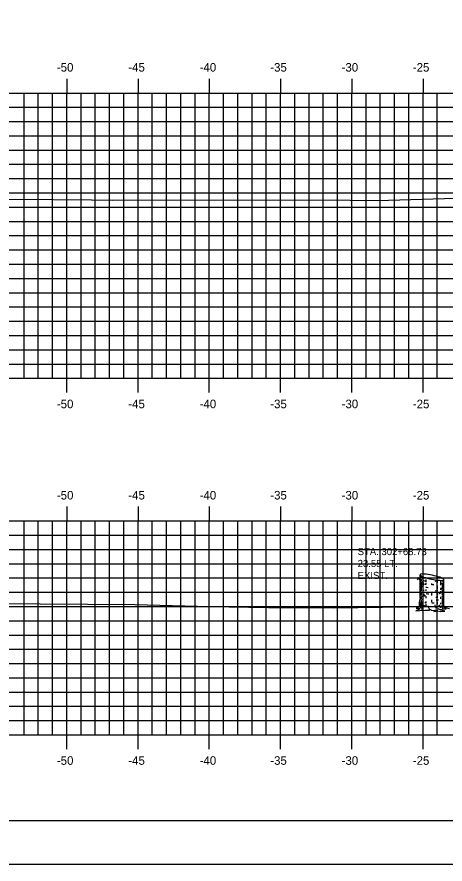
# Model space of a CAD drawing. Extents: x 1136767 to 1136937, y 608981 to 609091.
# Drawn here: x 1136796.9 to 1136826.9, y 608981.3 to 609040.7 of the extents above; entities that cross this region are included whole.
import ezdxf

# ---------------------------------------------------------------- set-up
doc = ezdxf.new("R2010")
doc.units = 0
for name, color, linetype in [('BORDER', 7, 'Continuous'), ('D_Text_Monospaced', 7, 'Continuous'), ('H_V ANNOTATION', 7, 'Continuous'), ('MAJOR', 7, 'Continuous'), ('MINOR', 7, 'Continuous'), ('PLOT BOUNDARY', 7, 'Continuous'), ('S_Roadway_Centerline', 7, 'Continuous'), ('S_Trees_Conifer_Pay', 7, 'Continuous')]:
    doc.layers.add(name, color=color, linetype=linetype)

msp = doc.modelspace()

# ---------------------------------------------------------------- linework, layer by layer
at = {"layer": 'BORDER'}
msp.add_lwpolyline([(1136775.383, 608984.335), (1136935.383, 608984.335), (1136935.383, 609089.335), (1136775.383, 609089.335)], close=True, dxfattribs=at)
at = {"layer": 'MAJOR'}
for p, q in [((1136800.383, 609036.337), (1136800.383, 609035.335)), ((1136805.383, 609036.337), (1136805.383, 609035.335)), ((1136810.383, 609036.337), (1136810.383, 609035.335)), ((1136815.383, 609036.337), (1136815.383, 609035.335)), ((1136820.383, 609036.337), (1136820.383, 609035.335)), ((1136825.383, 609036.337), (1136825.383, 609035.335)), ((1136780.383, 609035.335), (1136920.383, 609035.335)), ((1136780.383, 609035.335), (1136920.383, 609035.335)), ((1136800.383, 609015.335), (1136800.383, 609035.335)), ((1136805.383, 609015.335), (1136805.383, 609035.335)), ((1136810.383, 609015.335), (1136810.383, 609035.335)), ((1136815.383, 609015.335), (1136815.383, 609035.335)), ((1136820.383, 609015.335), (1136820.383, 609035.335)), ((1136825.383, 609015.335), (1136825.383, 609035.335)), ((1136780.383, 609030.335), (1136920.383, 609030.335)), ((1136780.383, 609025.335), (1136920.383, 609025.335)), ((1136780.383, 609020.335), (1136920.383, 609020.335)), ((1136780.383, 609015.335), (1136920.383, 609015.335)), ((1136780.383, 609015.335), (1136920.383, 609015.335)), ((1136800.383, 609014.333), (1136800.383, 609015.335)), ((1136805.383, 609014.333), (1136805.383, 609015.335)), ((1136810.383, 609014.333), (1136810.383, 609015.335)), ((1136815.383, 609014.333), (1136815.383, 609015.335)), ((1136820.383, 609014.333), (1136820.383, 609015.335)), ((1136825.383, 609014.333), (1136825.383, 609015.335)), ((1136800.383, 609006.337), (1136800.383, 609005.335)), ((1136805.383, 609006.337), (1136805.383, 609005.335)), ((1136810.383, 609006.337), (1136810.383, 609005.335)), ((1136815.383, 609006.337), (1136815.383, 609005.335)), ((1136820.383, 609006.337), (1136820.383, 609005.335)), ((1136825.383, 609006.337), (1136825.383, 609005.335)), ((1136780.383, 609005.335), (1136920.383, 609005.335)), ((1136780.383, 609005.335), (1136920.383, 609005.335)), ((1136800.383, 608990.335), (1136800.383, 609005.335)), ((1136805.383, 608990.335), (1136805.383, 609005.335)), ((1136810.383, 608990.335), (1136810.383, 609005.335)), ((1136815.383, 608990.335), (1136815.383, 609005.335)), ((1136820.383, 608990.335), (1136820.383, 609005.335)), ((1136825.383, 608990.335), (1136825.383, 609005.335)), ((1136780.383, 609000.335), (1136920.383, 609000.335)), ((1136780.383, 608995.335), (1136920.383, 608995.335)), ((1136780.383, 608990.335), (1136920.383, 608990.335)), ((1136780.383, 608990.335), (1136920.383, 608990.335)), ((1136800.383, 608989.333), (1136800.383, 608990.335)), ((1136805.383, 608989.333), (1136805.383, 608990.335)), ((1136810.383, 608989.333), (1136810.383, 608990.335)), ((1136815.383, 608989.333), (1136815.383, 608990.335)), ((1136820.383, 608989.333), (1136820.383, 608990.335)), ((1136825.383, 608989.333), (1136825.383, 608990.335))]:
    msp.add_line(p, q, dxfattribs=at)
at = {"layer": 'MINOR'}
for p, q in [((1136797.383, 609015.335), (1136797.383, 609035.335)), ((1136798.383, 609015.335), (1136798.383, 609035.335)), ((1136799.383, 609015.335), (1136799.383, 609035.335)), ((1136801.383, 609015.335), (1136801.383, 609035.335)), ((1136802.383, 609015.335), (1136802.383, 609035.335)), ((1136803.383, 609015.335), (1136803.383, 609035.335)), ((1136804.383, 609015.335), (1136804.383, 609035.335)), ((1136806.383, 609015.335), (1136806.383, 609035.335)), ((1136807.383, 609015.335), (1136807.383, 609035.335)), ((1136808.383, 609015.335), (1136808.383, 609035.335)), ((1136809.383, 609015.335), (1136809.383, 609035.335)), ((1136811.383, 609015.335), (1136811.383, 609035.335)), ((1136812.383, 609015.335), (1136812.383, 609035.335)), ((1136813.383, 609015.335), (1136813.383, 609035.335)), ((1136814.383, 609015.335), (1136814.383, 609035.335)), ((1136816.383, 609015.335), (1136816.383, 609035.335)), ((1136817.383, 609015.335), (1136817.383, 609035.335)), ((1136818.383, 609015.335), (1136818.383, 609035.335)), ((1136819.383, 609015.335), (1136819.383, 609035.335)), ((1136821.383, 609015.335), (1136821.383, 609035.335)), ((1136822.383, 609015.335), (1136822.383, 609035.335)), ((1136823.383, 609015.335), (1136823.383, 609035.335)), ((1136824.383, 609015.335), (1136824.383, 609035.335)), ((1136826.383, 609015.335), (1136826.383, 609035.335)), ((1136780.383, 609034.335), (1136920.383, 609034.335)), ((1136780.383, 609033.335), (1136920.383, 609033.335)), ((1136780.383, 609032.335), (1136920.383, 609032.335)), ((1136780.383, 609031.335), (1136920.383, 609031.335)), ((1136780.383, 609029.335), (1136920.383, 609029.335)), ((1136780.383, 609028.335), (1136920.383, 609028.335)), ((1136780.383, 609027.335), (1136920.383, 609027.335)), ((1136780.383, 609026.335), (1136920.383, 609026.335)), ((1136780.383, 609024.335), (1136920.383, 609024.335)), ((1136780.383, 609023.335), (1136920.383, 609023.335)), ((1136780.383, 609022.335), (1136920.383, 609022.335)), ((1136780.383, 609021.335), (1136920.383, 609021.335)), ((1136780.383, 609019.335), (1136920.383, 609019.335)), ((1136780.383, 609018.335), (1136920.383, 609018.335)), ((1136780.383, 609017.335), (1136920.383, 609017.335)), ((1136780.383, 609016.335), (1136920.383, 609016.335)), ((1136797.383, 608990.335), (1136797.383, 609005.335)), ((1136798.383, 608990.335), (1136798.383, 609005.335)), ((1136799.383, 608990.335), (1136799.383, 609005.335)), ((1136801.383, 608990.335), (1136801.383, 609005.335)), ((1136802.383, 608990.335), (1136802.383, 609005.335)), ((1136803.383, 608990.335), (1136803.383, 609005.335)), ((1136804.383, 608990.335), (1136804.383, 609005.335)), ((1136806.383, 608990.335), (1136806.383, 609005.335)), ((1136807.383, 608990.335), (1136807.383, 609005.335)), ((1136808.383, 608990.335), (1136808.383, 609005.335)), ((1136809.383, 608990.335), (1136809.383, 609005.335)), ((1136811.383, 608990.335), (1136811.383, 609005.335)), ((1136812.383, 608990.335), (1136812.383, 609005.335)), ((1136813.383, 608990.335), (1136813.383, 609005.335)), ((1136814.383, 608990.335), (1136814.383, 609005.335)), ((1136816.383, 608990.335), (1136816.383, 609005.335)), ((1136817.383, 608990.335), (1136817.383, 609005.335)), ((1136818.383, 608990.335), (1136818.383, 609005.335)), ((1136819.383, 608990.335), (1136819.383, 609005.335)), ((1136821.383, 608990.335), (1136821.383, 609005.335)), ((1136822.383, 608990.335), (1136822.383, 609005.335)), ((1136823.383, 608990.335), (1136823.383, 609005.335)), ((1136824.383, 608990.335), (1136824.383, 609005.335)), ((1136826.383, 608990.335), (1136826.383, 609005.335)), ((1136780.383, 609004.335), (1136920.383, 609004.335)), ((1136780.383, 609003.335), (1136920.383, 609003.335)), ((1136780.383, 609002.335), (1136920.383, 609002.335)), ((1136780.383, 609001.335), (1136920.383, 609001.335)), ((1136780.383, 608999.335), (1136920.383, 608999.335)), ((1136780.383, 608998.335), (1136920.383, 608998.335)), ((1136780.383, 608997.335), (1136920.383, 608997.335)), ((1136780.383, 608996.335), (1136920.383, 608996.335)), ((1136780.383, 608994.335), (1136920.383, 608994.335)), ((1136780.383, 608993.335), (1136920.383, 608993.335)), ((1136780.383, 608992.335), (1136920.383, 608992.335)), ((1136780.383, 608991.335), (1136920.383, 608991.335))]:
    msp.add_line(p, q, dxfattribs=at)
at = {"layer": 'PLOT BOUNDARY'}
msp.add_lwpolyline([(1136767.29, 608981.276), (1136937.29, 608981.276), (1136937.29, 609091.276), (1136767.29, 609091.276)], close=True, dxfattribs=at)
at = {"layer": 'S_Roadway_Centerline'}
for points in [[(1136780.383, 609027.49), (1136782.368, 609027.522), (1136796.751, 609027.884), (1136802.122, 609027.834), (1136803.598, 609027.827), (1136818.354, 609027.839), (1136822.194, 609027.792), (1136827.669, 609027.966)], [(1136780.383, 608999.708), (1136782.016, 608999.564), (1136790.64, 608999.588), (1136795.162, 608999.534), (1136805.193, 608999.485), (1136810.391, 608999.336), (1136814.548, 608999.253), (1136819.07, 608999.229), (1136827.733, 608999.346)]]:
    msp.add_lwpolyline(points, dxfattribs=at)
at = {"layer": 'S_Trees_Conifer_Pay'}
for p, q in [((1136825.173, 608999.911), (1136825.173, 609001.558)), ((1136825.244, 609001.486), (1136825.244, 609001.323)), ((1136825.244, 609001.255), (1136825.244, 609001.127)), ((1136825.244, 609000.94), (1136825.244, 609000.604)), ((1136825.305, 609000.93), (1136825.356, 609000.87)), ((1136825.362, 609001.425), (1136825.362, 609001.201)), ((1136825.362, 609001.113), (1136825.362, 609001.066)), ((1136825.59, 609001.228), (1136825.59, 609001.029)), ((1136825.59, 609000.971), (1136825.59, 609000.883)), ((1136825.98, 609000.955), (1136825.98, 609000.86)), ((1136826.386, 609001.186), (1136826.386, 609001.018)), ((1136826.606, 609001.166), (1136826.606, 609000.934)), ((1136826.731, 609001.174), (1136826.731, 609001.076)), ((1136826.731, 609001.002), (1136826.731, 609000.798)), ((1136826.79, 609001.185), (1136826.79, 609000.714)), ((1136826.837, 608999.501), (1136826.837, 609001.222)), ((1136825.244, 609000.568), (1136825.244, 609000.405)), ((1136825.244, 609000.358), (1136825.244, 609000.141)), ((1136825.362, 609000.73), (1136825.362, 609000.598)), ((1136825.362, 609000.488), (1136825.362, 609000.378)), ((1136825.59, 609000.535), (1136825.59, 609000.43)), ((1136825.98, 609000.341), (1136825.98, 609000.267)), ((1136826.386, 609000.782), (1136826.386, 609000.545)), ((1136826.606, 609000.893), (1136826.606, 609000.819)), ((1136826.606, 609000.415), (1136826.606, 609000.277)), ((1136826.731, 609000.74), (1136826.731, 609000.541)), ((1136826.731, 609000.493), (1136826.731, 609000.158)), ((1136826.79, 609000.65), (1136826.79, 609000.341)), ((1136825.244, 609000.11), (1136825.244, 609000.036)), ((1136825.244, 608999.995), (1136825.244, 608999.822)), ((1136825.362, 609000.242), (1136825.362, 609000.1)), ((1136825.362, 608999.873), (1136825.362, 608999.701)), ((1136825.59, 609000.063), (1136825.59, 608999.917)), ((1136825.98, 609000.242), (1136825.98, 609000.094)), ((1136825.98, 608999.802), (1136825.98, 608999.649)), ((1136826.386, 609000.3), (1136826.386, 609000.148)), ((1136826.386, 609000.104), (1136826.386, 608999.931)), ((1136826.606, 609000.005), (1136826.606, 608999.864)), ((1136826.731, 609000.104), (1136826.731, 608999.969)), ((1136826.731, 608999.869), (1136826.731, 608999.491)), ((1136826.79, 609000.294), (1136826.79, 608999.802)), ((1136826.79, 608999.748), (1136826.79, 608999.501)), ((1136825.59, 608999.684), (1136825.59, 608999.596)), ((1136826.386, 608999.654), (1136826.386, 608999.501)), ((1136826.606, 608999.108), (1136826.443, 608999.171)), ((1136826.606, 608999.602), (1136826.606, 608999.507)), ((1136826.169, 608999.043), (1136826.295, 608999.108))]:
    msp.add_line(p, q, dxfattribs=at)
for points in [[(1136825.127, 609001.289), (1136825.051, 609001.297), (1136824.979, 609001.198)], [(1136825.356, 609001.056), (1136825.319, 609000.982), (1136825.272, 609001.039), (1136825.214, 609001.107), (1136825.122, 609001.301), (1136825.057, 609001.348), (1136825.026, 609001.354)], [(1136825.341, 609000.803), (1136825.305, 609000.93), (1136825.241, 609001.045), (1136825.21, 609001.113), (1136825.141, 609001.259)], [(1136825.389, 609001.018), (1136825.42, 609000.934), (1136825.424, 609000.866), (1136825.393, 609000.803)], [(1136826.658, 609000.528), (1136826.664, 609000.623), (1136826.62, 609000.6), (1136826.62, 609000.506)], [(1136825.173, 608999.911), (1136825.122, 608999.649), (1136825.105, 608999.375), (1136825.047, 608999.25), (1136824.912, 608999.219), (1136825.142, 608999.182), (1136825.142, 608999.182), (1136825.136, 608999.135), (1136824.889, 608999.04), (1136825.163, 608999.056), (1136825.519, 608999.077), (1136825.84, 608999.066), (1136825.833, 608999.149), (1136825.982, 608999.066), (1136826.169, 608999.043), (1136826.145, 608998.976), (1136826.412, 608999.019), (1136826.633, 608998.992), (1136826.925, 608999.009), (1136826.637, 608999.066), (1136826.606, 608999.108), (1136826.769, 608999.165), (1136827.005, 608999.176)], [(1136825.247, 608999.768), (1136825.241, 608999.623), (1136825.194, 608999.555), (1136825.183, 608999.355)], [(1136825.519, 609000.129), (1136825.506, 609000.053), (1136825.459, 609000.063), (1136825.471, 609000.23)], [(1136825.346, 608999.623), (1136825.272, 608999.518), (1136825.267, 608999.345), (1136825.142, 608999.182)], [(1136825.305, 608999.129), (1136825.319, 608999.266), (1136825.393, 608999.396)], [(1136825.583, 608999.518), (1136825.572, 608999.392), (1136825.498, 608999.348)], [(1136825.833, 608999.149), (1136825.759, 608999.291), (1136825.749, 608999.392)], [(1136826.322, 608999.219), (1136826.254, 608999.314), (1136826.227, 608999.453)], [(1136826.548, 608999.46), (1136826.548, 608999.328), (1136826.637, 608999.229)], [(1136826.711, 608999.433), (1136826.705, 608999.318), (1136826.758, 608999.229), (1136826.769, 608999.165)], [(1136826.789, 608999.453), (1136826.81, 608999.375), (1136826.83, 608999.281)], [(1136827.246, 608999.176), (1136826.904, 608999.234), (1136826.863, 608999.314), (1136826.837, 608999.501)]]:
    msp.add_lwpolyline(points, dxfattribs=at)
for centre, radius, start, end in [((1136825.195, 609001.558), 0.0226, 156.59265, 168.2806), ((1136825.195, 609001.558), 0.0226, 168.2806, 179.96855), ((1136825.199, 609001.558), 0.0264, 179.96855, 190.7806), ((1136825.204, 609001.559), 0.0314, 190.7806, 203.48418), ((1136825.199, 609001.556), 0.0264, 145.7806, 156.59265), ((1136825.224, 609001.567), 0.0527, 203.48418, 213.2806), ((1136825.203, 609001.554), 0.0314, 133.07702, 145.7806), ((1136825.248, 609001.583), 0.0817, 213.2806, 227.61132), ((1136825.217, 609001.538), 0.0527, 123.2806, 133.07702), ((1136825.233, 609001.514), 0.0817, 108.94987, 123.2806), ((1136825.362, 609001.708), 0.251, 227.61132, 235.7806), ((1136825.288, 609001.354), 0.251, 100.7806, 108.94987), ((1136825.391, 609000.813), 0.802, 84.62059, 100.7806), ((1136824.981, 608996.455), 5.179, 78.2806, 84.62059), ((1136824.981, 608996.455), 5.179, 71.94061, 78.2806), ((1136825.206, 609001.432), 0.0334, 185.78494, 196.05154), ((1136825.206, 609001.277), 0.0334, 185.78494, 196.05154), ((1136825.216, 609001.435), 0.0441, 196.05154, 210), ((1136825.216, 609001.28), 0.0441, 196.05154, 210), ((1136825.232, 609001.444), 0.0624, 210, 228.74941), ((1136825.232, 609001.289), 0.0624, 210, 228.74941), ((1136825.304, 609001.526), 0.172, 228.74941, 240), ((1136825.304, 609001.372), 0.172, 228.74941, 240), ((1136825.504, 609001.717), 0.571, 240, 242.9763), ((1136825.671, 609002.164), 0.802, 235.7806, 251.94061), ((1136825.504, 609001.871), 0.571, 247.58675, 255.56834), ((1136825.504, 609001.717), 0.571, 255.63335, 261.8968), ((1136827.028, 609006.325), 5.179, 251.94061, 258.2806), ((1136826.004, 609005.234), 4.124, 261.8968, 263.76196), ((1136827.028, 609006.325), 5.179, 258.2806, 264.62059), ((1136826.004, 609005.234), 4.124, 273.26691, 275.3045), ((1136826.618, 609001.967), 0.802, 264.62059, 280.7806), ((1136826.338, 609000.617), 0.802, 55.7806, 71.94061), ((1136826.507, 609001.484), 0.571, 282.01543, 293.14027), ((1136826.721, 609001.426), 0.251, 280.7806, 288.94988), ((1136826.648, 609001.072), 0.251, 47.61132, 55.7806), ((1136826.507, 609001.484), 0.571, 299.66328, 300), ((1136826.706, 609001.139), 0.172, 300, 311.25059), ((1136826.776, 609001.266), 0.0817, 288.94988, 303.2806), ((1136826.762, 609001.197), 0.0817, 33.2806, 47.61132), ((1136826.778, 609001.056), 0.0624, 311.25059, 330), ((1136826.792, 609001.242), 0.0527, 303.2806, 313.07702), ((1136826.806, 609001.226), 0.0314, 313.07702, 325.7806), ((1136826.786, 609001.213), 0.0527, 23.48418, 33.2806), ((1136826.811, 609001.224), 0.0264, 325.7806, 336.59265), ((1136826.794, 609001.047), 0.0441, 330, 343.94846), ((1136826.805, 609001.221), 0.0314, 10.7806, 23.48418), ((1136826.814, 609001.222), 0.0226, 336.59265, 348.2806), ((1136826.81, 609001.222), 0.0264, 359.96855, 10.7806), ((1136826.814, 609001.222), 0.0226, 348.2806, 359.96855), ((1136826.805, 609001.044), 0.0334, 0, 16.05154), ((1136826.805, 609001.044), 0.0334, 343.94846, 360), ((1136825.206, 609000.833), 0.0334, 185.78494, 196.05154), ((1136825.207, 609000.597), 0.0334, 185.78494, 196.05154), ((1136825.207, 609000.387), 0.0334, 185.78494, 196.05154), ((1136825.218, 609000.6), 0.0441, 196.05154, 210), ((1136825.218, 609000.39), 0.0441, 196.05154, 210), ((1136825.233, 609000.61), 0.0624, 210, 228.74941), ((1136825.233, 609000.4), 0.0624, 210, 228.74941), ((1136825.306, 609000.692), 0.172, 228.74941, 240), ((1136825.306, 609000.482), 0.172, 228.74941, 240), ((1136825.505, 609001.037), 0.571, 240, 242.81041), ((1136825.505, 609000.827), 0.571, 240, 242.81041), ((1136825.504, 609001.273), 0.571, 242.95715, 255.55072), ((1136825.505, 609001.037), 0.571, 253.07038, 261.8968), ((1136826.006, 609004.555), 4.124, 261.8968, 262.38753), ((1136826.006, 609005.002), 4.124, 262.94416, 264.21507), ((1136826.005, 609004.79), 4.124, 264.04957, 266.29476), ((1136826.006, 609005.002), 4.124, 269.64186, 270), ((1136826.006, 609005.002), 4.124, 270, 271.92488), ((1136826.006, 609004.555), 4.124, 273.33241, 275.91902), ((1136826.505, 609001.273), 0.571, 292.94134, 300), ((1136826.507, 609000.827), 0.571, 293.14027, 300), ((1136826.507, 609001.037), 0.571, 299.66328, 300), ((1136826.706, 609000.692), 0.172, 300, 311.25059), ((1136826.706, 609000.482), 0.172, 300, 311.25059), ((1136826.778, 609000.61), 0.0624, 311.25059, 330), ((1136826.778, 609000.4), 0.0624, 311.25059, 330), ((1136826.794, 609000.6), 0.0441, 330, 343.94846), ((1136826.794, 609000.39), 0.0441, 330, 343.94846), ((1136826.805, 609000.597), 0.0334, 0, 16.05154), ((1136826.805, 609000.597), 0.0334, 343.94846, 360), ((1136826.805, 609000.387), 0.0334, 0, 16.05154), ((1136826.805, 609000.387), 0.0334, 343.94846, 360), ((1136825.207, 608999.953), 0.0334, 185.78494, 196.05154), ((1136825.218, 608999.956), 0.0441, 196.05154, 210), ((1136825.233, 608999.965), 0.0624, 210, 228.74941), ((1136825.306, 609000.048), 0.172, 228.74941, 240), ((1136825.505, 609000.393), 0.571, 240, 250.70928), ((1136825.505, 609000.59), 0.571, 242.81041, 254.60173), ((1136826.006, 609004.345), 4.124, 264.54309, 266.85066), ((1136826.006, 609004.345), 4.124, 269.64186, 270), ((1136826.006, 609004.108), 4.124, 273.68066, 275.28397), ((1136826.006, 609003.91), 4.124, 274.16025, 276.50094), ((1136826.006, 609004.345), 4.124, 276.85262, 278.1032), ((1136826.507, 609000.827), 0.571, 278.1032, 280.72928), ((1136826.507, 609000.59), 0.571, 293.14027, 300), ((1136826.518, 609000.399), 0.571, 291.97323, 298.76314), ((1136826.706, 609000.245), 0.172, 300, 311.25059), ((1136826.778, 609000.163), 0.0624, 311.25059, 330), ((1136826.778, 608999.769), 0.0624, 311.25059, 330), ((1136826.794, 609000.154), 0.0441, 330, 343.94846), ((1136826.794, 608999.76), 0.0441, 330, 343.94846), ((1136826.805, 609000.151), 0.0334, 0, 16.05154), ((1136826.805, 609000.151), 0.0334, 343.94846, 360), ((1136826.805, 608999.953), 0.0334, 0, 16.05154), ((1136826.805, 608999.757), 0.0334, 0, 16.05154), ((1136826.805, 608999.757), 0.0334, 343.94846, 360), ((1136825.207, 608999.537), 0.0334, 185.78494, 196.05154), ((1136825.218, 608999.54), 0.0441, 196.05154, 210), ((1136825.233, 608999.549), 0.0624, 210, 228.74941), ((1136825.306, 608999.632), 0.172, 228.74941, 240), ((1136825.505, 609000.197), 0.571, 242.72792, 251.49327), ((1136825.505, 608999.977), 0.571, 258.36297, 261.8968), ((1136826.006, 609003.494), 4.124, 261.8968, 262.63158), ((1136826.006, 609003.715), 4.124, 263.21039, 264.21507), ((1136826.006, 609003.715), 4.124, 269.86721, 270), ((1136826.006, 609003.715), 4.124, 270, 272.18834), ((1136826.006, 609003.494), 4.124, 276.48798, 277.55621), ((1136826.507, 609000.197), 0.571, 293.14027, 300), ((1136826.507, 608999.977), 0.571, 295.46862, 300), ((1136826.706, 608999.852), 0.172, 300, 311.25059), ((1136826.706, 608999.632), 0.172, 300, 311.25059), ((1136826.778, 608999.549), 0.0624, 311.25059, 330), ((1136826.794, 608999.54), 0.0441, 330, 343.94846), ((1136826.805, 608999.537), 0.0334, 0, 16.05154), ((1136826.805, 608999.537), 0.0334, 343.94846, 360)]:
    msp.add_arc(centre, radius, start, end, dxfattribs=at)

# ---------------------------------------------------------------- texts
at = {"layer": 'D_Text_Monospaced'}
for s, height, p in [('STA. 302+68.73', 0.49998, (1136820.796, 609002.935)), ('23.55 LT.', 0.5, (1136820.796, 609002.101)), ('EXIST. ', 0.5, (1136820.796, 609001.261))]:
    msp.add_text(s, height=height, dxfattribs=at).set_placement(p)
at = {"layer": 'H_V ANNOTATION'}
for s, p in [('-50', (1136799.687, 609036.835)), ('-45', (1136804.701, 609036.835)), ('-40', (1136809.709, 609036.835)), ('-35', (1136814.663, 609036.835)), ('-30', (1136819.671, 609036.835)), ('-25', (1136824.669, 609036.835)), ('-50', (1136799.687, 609013.235)), ('-45', (1136804.701, 609013.235)), ('-40', (1136809.709, 609013.235)), ('-35', (1136814.663, 609013.235)), ('-30', (1136819.671, 609013.235)), ('-25', (1136824.669, 609013.235)), ('-50', (1136799.687, 609006.835)), ('-45', (1136804.701, 609006.835)), ('-40', (1136809.709, 609006.835)), ('-35', (1136814.663, 609006.835)), ('-30', (1136819.671, 609006.835)), ('-25', (1136824.669, 609006.835)), ('-50', (1136799.687, 608988.235)), ('-45', (1136804.701, 608988.235)), ('-40', (1136809.709, 608988.235)), ('-35', (1136814.663, 608988.235)), ('-30', (1136819.671, 608988.235)), ('-25', (1136824.669, 608988.235))]:
    msp.add_text(s, height=0.6, dxfattribs=at).set_placement(p)

doc.saveas('drawing.dxf')
